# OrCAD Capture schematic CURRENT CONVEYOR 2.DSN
size A
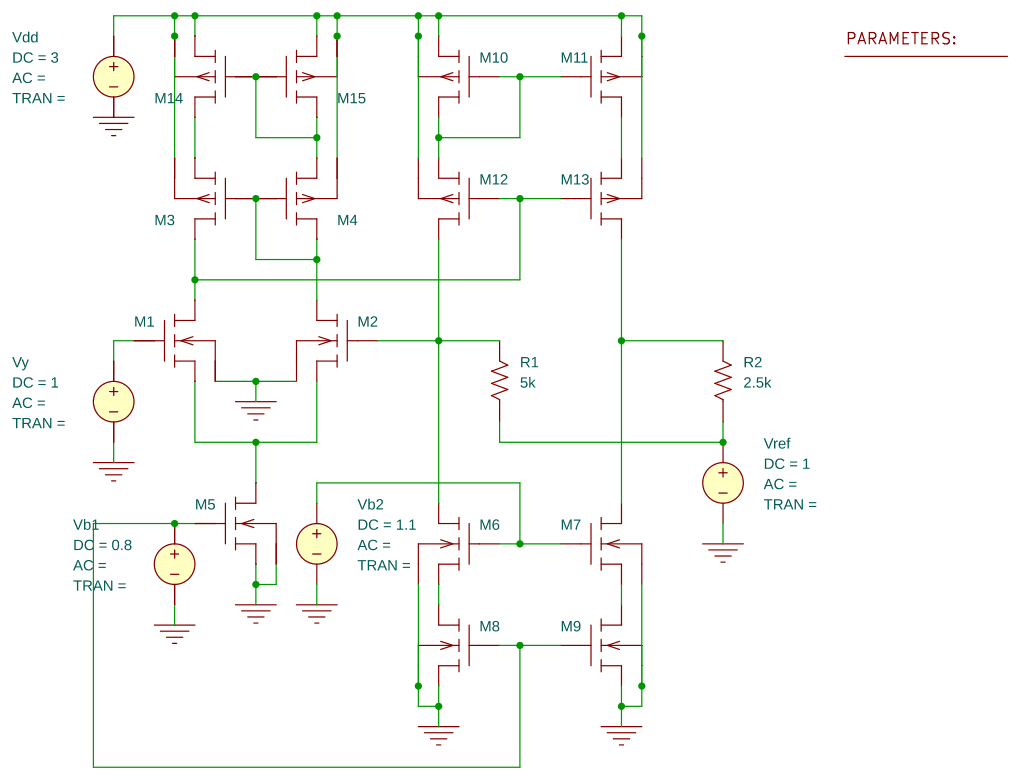
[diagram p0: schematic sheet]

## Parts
1  PARAM
M1  MbreakN
M2  MbreakN
M3  MbreakP
M4  MbreakP
M5  MbreakN
M6  MbreakN
M7  MbreakN
M8  MbreakN
M9  MbreakN
M10  MbreakP
M11  MbreakP
M12  MbreakP
M13  MbreakP
M14  MbreakP
M15  MbreakP
R1  5k  [AX/RC05]
R2  2.5k  [AX/RC05]
Vb1  VSRC
Vb2  VSRC
Vdd  VSRC
Vref  VSRC
Vy  VSRC

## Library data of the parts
1 = PARAM: W1: 70u; W10: 420u; W11: 420u; W12: 420u; W13: 420u; W14: 100u; W15: 100u; W2: 70u; W3: 100u; W4: 100u; W5: 14u; W6: 140u; W7: 140u; W8: 50u; W9: 50u
M1 = MbreakN: AD: {3*0.35u*W1}; AS: {3*0.35u*W1}; L: 0.35u; PD: {W1+6*0.35u}; PS: {W1+6*0.35u}; W: 70u
M2 = MbreakN: AD: {3*0.35u*W2}; AS: {3*0.35u*W2}; L: 0.35u; PD: {W2+6*0.35u}; PS: {W2+6*0.35u}; W: {W2}
M3 = MbreakP: AD: {3*0.35u*W3}; AS: {3*0.35u*W3}; L: 0.7u; PD: {W3+6*0.35u}; PS: {W3+6*0.35u}; W: {W3}
M4 = MbreakP: AD: {3*0.35u*W4}; AS: {3*0.35u*W4}; L: 0.7u; PD: {W4+6*0.35u}; PS: {W4+6*0.35u}; W: {W4}
M5 = MbreakN: AD: {3*0.35u*W5}; AS: {3*0.35u*W5}; L: 0.7u; PD: {W5+6*0.35u}; PS: {W5+6*0.35u}; W: {W5}
M6 = MbreakN: AD: {3*0.35u*W6}; AS: {3*0.35u*W6}; L: 0.7u; PD: {W6+6*0.35u}; PS: {W6+6*0.35u}; W: {W6}
M7 = MbreakN: AD: {3*0.35u*W7}; AS: {3*0.35u*W7}; L: 0.7u; PD: {W7+6*0.35u}; PS: {W7+6*0.35u}; W: {W7}
M8 = MbreakN: AD: {3*0.35u*W8}; AS: {3*0.35u*W8}; L: 0.7u; PD: {W8+6*0.35u}; PS: {W8+6*0.35u}; W: {W8}
M9 = MbreakN: AD: {3*0.35u*W9}; AS: {3*0.35u*W9}; L: 0.7u; PD: {W9+6*0.35u}; PS: {W9+6*0.35u}; W: {W9}
M10 = MbreakP: AD: {3*0.35u*W10}; AS: {3*0.35u*W10}; L: 0.7u; PD: {W10+6*0.35u}; PS: {W10+6*0.35u}; W: {W10}
M11 = MbreakP: AD: {3*0.35u*W11}; AS: {3*0.35u*W11}; L: 0.7u; PD: {W11+6*0.35u}; PS: {W11+6*0.35u}; W: {W11}
M12 = MbreakP: AD: {3*0.35u*W12}; AS: {3*0.35u*W12}; L: 0.7u; PD: {W12+6*0.35u}; PS: {W12+6*0.35u}; W: {W12}
M13 = MbreakP: AD: {3*0.35u*W13}; AS: {3*0.35u*W13}; L: 0.7u; PD: {W13+6*0.35u}; PS: {W13+6*0.35u}; W: {W13}
M14 = MbreakP: AD: {3*0.35u*W14}; AS: {3*0.35u*W14}; L: 0.7u; PD: {W14+6*0.35u}; PS: {W14+6*0.35u}; W: {W14}
M15 = MbreakP: AD: {3*0.35u*W15}; AS: {3*0.35u*W15}; L: 0.7u; PD: {W15+6*0.35u}; PS: {W15+6*0.35u}; W: {W15}
R1 R2 = R
Vb1 = VSRC: DC: 0.8
Vb2 = VSRC: DC: 1.1
Vdd = VSRC: DC: 3
Vref Vy = VSRC: DC: 1

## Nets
0: M1.4(b) M2.4(b) M5.0(s) M5.4(b) M6.4(b) M7.4(b) M8.0(s) M8.4(b) M9.0(s) M9.4(b) Vb1.1(-) Vb2.1(-) Vdd.1(-) Vref.1(-) Vy.1(-)
N00211: M1.0(s) M2.0(s) M5.2(d)
N00290: M2.2(d) M3.0(g) M4.0(g) M4.2(d)
N00325: M1.2(d) M3.2(d) M12.0(g) M13.0(g)
N00491: M3.4(b) M4.4(b) M10.1(s) M10.4(b) M11.1(s) M11.4(b) M12.4(b) M13.4(b) M14.1(s) M14.4(b) M15.1(s) M15.4(b) Vdd.0(+)
N00539: M4.1(s) M14.0(g) M15.0(g) M15.2(d)
N00564: M3.1(s) M14.2(d)
N01146: M7.0(s) M9.2(d)
N01241: M1.1(g) Vy.0(+)
N01321: M7.2(d) M13.2(d) R2.2
N01426: M5.1(g) M8.1(g) M9.1(g) Vb1.0(+)
N06776: M11.2(d) M13.1(s)
N08840: M2.1(g) M6.2(d) M12.2(d) R1.2
N09234: M6.1(g) M7.1(g) Vb2.0(+)
N10667: M6.0(s) M8.2(d)
N11255: M10.0(g) M10.2(d) M11.0(g) M12.1(s)
N18908: R1.1 R2.1 Vref.0(+)
